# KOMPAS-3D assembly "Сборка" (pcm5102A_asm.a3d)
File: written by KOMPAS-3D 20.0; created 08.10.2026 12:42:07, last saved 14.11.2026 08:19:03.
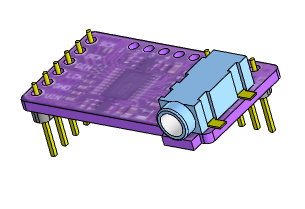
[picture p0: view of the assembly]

Document properties: Полное имя файла: D:\myProjects\Progect_esp32\box_compas\цап ацп\pcm5102A_asm.a3d

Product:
- Part/product: Сборка
    Масса: 0.00980212
  - Component [detail]: Деталь  | Масса: 0.00239431; source file: ..\разъемы\PJ-327A.m3d
  - Component [detail]: Деталь  | Масса: 0.00613645; source file: pcm5102A.m3d
  - Component [detail]: Деталь  | Масса: 0.000766031; source file: ..\разъемы\pls_6.m3d
  - Component [detail]: Деталь  | Масса: 0.000505328; source file: ..\разъемы\pls_4.m3d

Referenced files in D:\myProjects\Progect_esp32\box_compas\цап ацп\: pcm5102A.m3d
Referenced files in D:\myProjects\Progect_esp32\box_compas\разъемы\: pls_6.m3d, pls_4.m3d, PJ-327A.m3d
